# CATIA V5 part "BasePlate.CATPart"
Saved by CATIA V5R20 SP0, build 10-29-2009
Part number: BasePlate
Bounding box of the stored display mesh (mm): x -75 to 75, y -75 to 75, z -20 to 0
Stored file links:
  C:\Users\Robin\Desktop\Delar\BasePlate.CATPart
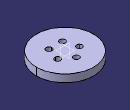
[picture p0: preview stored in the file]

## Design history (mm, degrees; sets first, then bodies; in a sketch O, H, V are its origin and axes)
Body1 (main body)
  DatumCurve1 to DatumCurve5
  Sketch1 on xy-plane, origin (0, 0, 0), H (1, 0, 0), V (0, 1, 0)
    circle A1 centre (0, 0) radius 75
    point P1 (0, 0)
    projected circle E1 centre (-17.6336, -24.2705) radius 7.5 from edge of DatumCurve1
    projected circle E2 centre (-28.5317, 9.2705) radius 7.5 from edge of DatumCurve2
    projected circle E3 centre (17.6336, -24.2705) radius 7.5 from edge of DatumCurve3
    projected circle E4 centre (28.5317, 9.2705) radius 7.5 from edge of DatumCurve4
    projected circle E5 centre (0, 30) radius 7.5 from edge of DatumCurve5
    radius A1 = 75
    coincidence: O P1
  Pad1: profile Sketch1, direction (0, 0, -1), length 20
